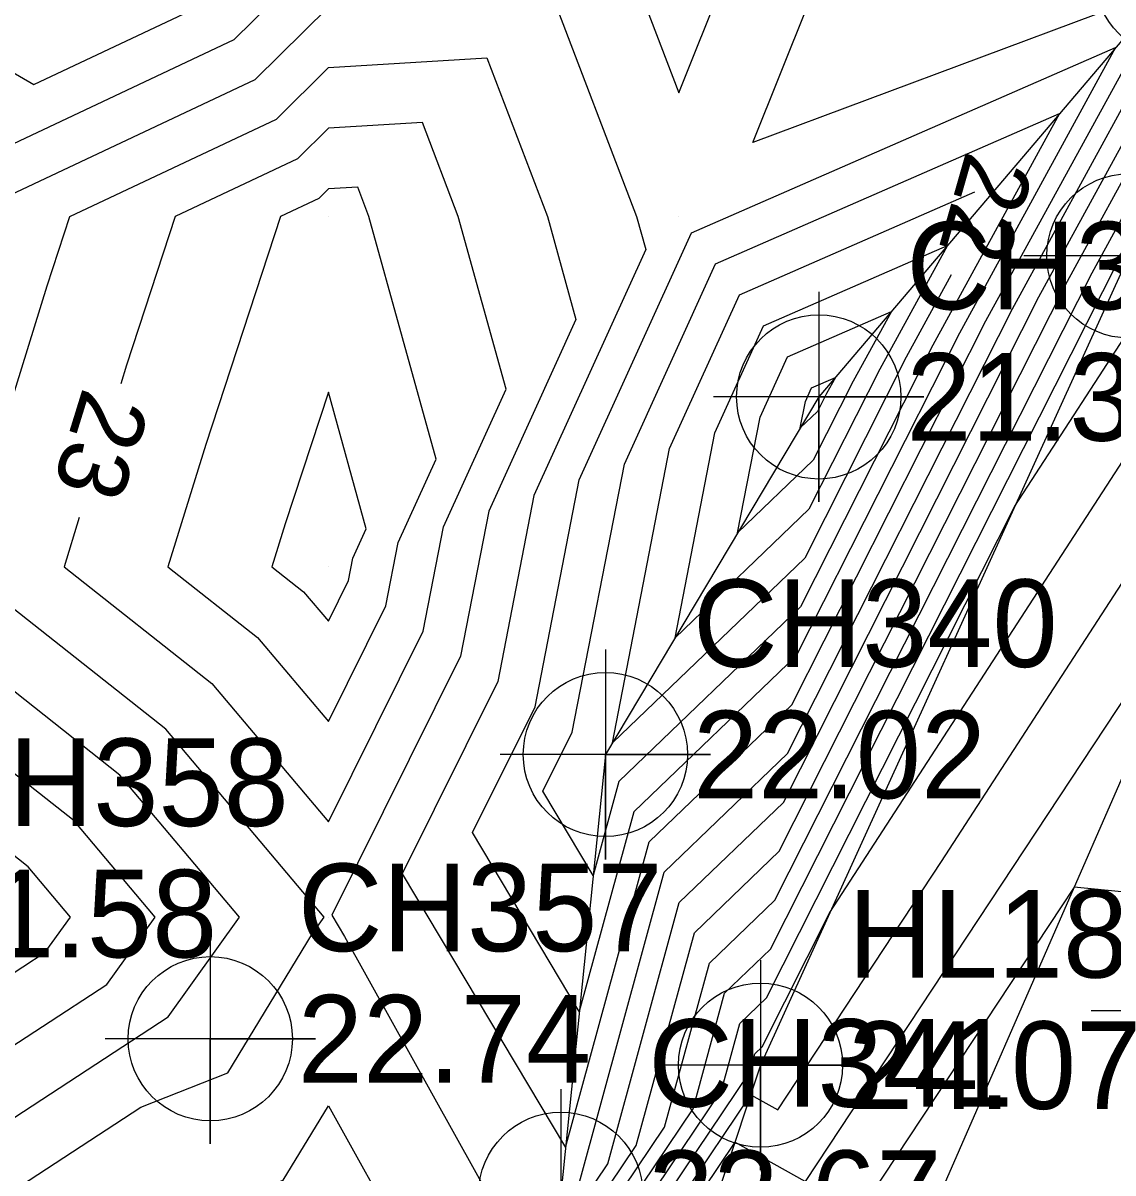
# Model space of a CAD drawing. Extents: x 2531902 to 2533249, y 715219 to 716099.
# Drawn here: x 2532801.29 to 2532832.39, y 715572.69 to 715605.53 of the extents above; entities that cross this region are included whole.
import ezdxf

# ---------------------------------------------------------------- set-up
doc = ezdxf.new("R2010")
doc.units = 0
for name, color, linetype in [('DTM Contours Major', 7, 'Continuous'), ('DTM Contours Major Text', 7, 'Continuous'), ('DTM Contours Minor', 7, 'Continuous'), ('Exist DTM Breakline', 7, 'Continuous'), ('Exist DTM Breakline Cogo Elevation', 7, 'Continuous'), ('Exist DTM Breakline Cogo Number', 7, 'Continuous'), ('Exist DTM Breakline Cogo Point CELL', 7, 'Continuous'), ('Exist DTM Drainline', 7, 'Continuous'), ('Exist DTM QL2 LIDAR Elevation Point', 7, 'Continuous'), ('Exist DTM Regular Point CELL', 7, 'Continuous'), ('Exist DTM Regular Point Cogo Elevation', 7, 'Continuous'), ('Exist DTM Regular Point Cogo Number', 7, 'Continuous'), ('Exist Roads Soil Cogo Point CELL', 7, 'Continuous')]:
    doc.layers.add(name, color=color, linetype=linetype)

msp = doc.modelspace()

# ---------------------------------------------------------------- linework, layer by layer
at = {"layer": 'DTM Contours Major'}
for points in [[(2532791.4, 715554.435), (2532792.067, 715557.933), (2532792.869, 715560), (2532794.025, 715565.975), (2532800, 715568.961), (2532800.889, 715569.111), (2532802.4, 715570), (2532808.714, 715572.49), (2532810, 715574.608), (2532812.181, 715570.686), (2532814.067, 715567.411), (2532813.398, 715561.929), (2532816.552, 715570.834), (2532817.976, 715572.954), (2532820.015, 715580.415), (2532822.987, 715583.272), (2532830.281, 715597.708), (2532833.72, 715603.995), (2532839.452, 715610.247), (2532839.495, 715610.298)], [(2532813.283, 715591.138), (2532815.07, 715595.07), (2532813.705, 715600), (2532812.683, 715602.683), (2532810, 715602.519), (2532809.121, 715601.649), (2532805.628, 715600), (2532804.242, 715595.758), (2532804.076, 715595.225)], [(2532818.106, 715584.973), (2532819.74, 715593.375), (2532821.734, 715597.765), (2532828.453, 715600.702)], [(2532827.776, 715598.331), (2532826.493, 715595.986), (2532823.595, 715590.25), (2532818.106, 715584.973)], [(2532816.309, 715567.061), (2532822.029, 715575.574), (2532822.171, 715576.095), (2532822.379, 715576.294), (2532824.314, 715580.125), (2532834.07, 715595.172)], [(2532802.892, 715591.404), (2532802.457, 715590), (2532806.67, 715586.67), (2532810, 715582.721), (2532812.706, 715588.166), (2532813.283, 715591.138)]]:
    msp.add_lwpolyline(points, dxfattribs=at)
at = {"layer": 'DTM Contours Minor'}
for points in [[(2532800, 715604.694), (2532801.593, 715603.77), (2532806.704, 715606.184), (2532810, 715609.445), (2532819.083, 715610), (2532820.17, 715610.294), (2532824.846, 715615.648), (2532828.788, 715619.347), (2532829.955, 715620.078), (2532830.004, 715620.089), (2532836.592, 715620.993)], [(2532816.26, 715566.306), (2532822.053, 715574.927), (2532822.823, 715574.495), (2532827.503, 715581.581), (2532834.828, 715592.88), (2532842.241, 715605.151), (2532843.096, 715603.185), (2532845.749, 715611.189), (2532851.137, 715619.865), (2532853.378, 715619.981), (2532856.522, 715615.626), (2532856.577, 715608.1), (2532858.751, 715598.418), (2532859.746, 715597.674), (2532860.482, 715597.724), (2532858.698, 715593.363), (2532858.5, 715592.772), (2532854.09, 715579.617), (2532854.851, 715576.054), (2532852.242, 715565.505)], [(2532800.095, 715600.225), (2532807.913, 715603.916), (2532810, 715605.982), (2532816.371, 715606.371), (2532818.797, 715600), (2532819.058, 715599.058), (2532815.866, 715592.033), (2532814.834, 715586.723), (2532812.107, 715581.236), (2532816.768, 715573.416), (2532819.153, 715582.143), (2532823.23, 715586.063), (2532828.765, 715597.019), (2532834.068, 715606.71), (2532831.907, 715605.766), (2532822.113, 715602.113), (2532825.275, 715610), (2532827.585, 715612.646), (2532830, 715614.912), (2532835.701, 715619.851)], [(2532800.844, 715601.998), (2532807.309, 715605.05), (2532810, 715607.714), (2532818.215, 715608.215), (2532820, 715603.529), (2532822.594, 715610), (2532826.216, 715614.147), (2532830, 715617.698), (2532832.579, 715619.933)], [(2532847.705, 715569.849), (2532849.505, 715575.216), (2532853.41, 715594.081), (2532853.465, 715594.349), (2532852.389, 715599.142), (2532852.28, 715613.906), (2532851.071, 715615.58), (2532850.209, 715615.536), (2532848.137, 715612.199), (2532843.88, 715599.358), (2532844.511, 715592.438), (2532839.033, 715587.843), (2532835.553, 715590.397), (2532835.464, 715590.406), (2532823.606, 715572.454), (2532821.604, 715573.577), (2532816.212, 715565.552)], [(2532817.165, 715572.43), (2532819.584, 715581.279), (2532823.108, 715584.668), (2532829.523, 715597.363), (2532833.979, 715605.508)], [(2532820.362, 715599.533), (2532832.468, 715604.827), (2532828.008, 715596.674), (2532823.352, 715587.459), (2532818.721, 715583.008), (2532817.162, 715577.302), (2532814.115, 715582.414), (2532815.898, 715586.002), (2532817.157, 715592.48), (2532820.362, 715599.533)], [(2532800, 715591.644), (2532801.977, 715598.023), (2532802.623, 715600), (2532808.517, 715602.783), (2532810, 715604.251), (2532814.527, 715604.527), (2532816.251, 715600), (2532817.064, 715597.064), (2532814.575, 715591.585), (2532813.77, 715587.444), (2532810.099, 715580.058), (2532810.463, 715579.447), (2532814.867, 715571.53)], [(2532821.048, 715598.649), (2532830.868, 715602.943), (2532827.25, 715596.33), (2532823.473, 715588.855), (2532818.29, 715583.872), (2532817.557, 715581.187), (2532816.123, 715583.593), (2532816.962, 715585.28), (2532818.448, 715592.928), (2532821.048, 715598.649)], [(2532816.503, 715570.08), (2532818.787, 715573.478), (2532820.446, 715579.551), (2532822.865, 715581.877), (2532831.038, 715598.052), (2532833.462, 715602.482)], [(2532816.455, 715569.325), (2532819.597, 715574.002), (2532820.878, 715578.687), (2532822.743, 715580.481), (2532831.796, 715598.397), (2532833.203, 715600.969)], [(2532811.992, 715590.69), (2532813.076, 715593.076), (2532811.158, 715600), (2532810.839, 715600.839), (2532810, 715600.787), (2532809.725, 715600.516), (2532808.633, 715600), (2532806.506, 715593.494), (2532805.423, 715590), (2532807.98, 715587.98), (2532810, 715585.584), (2532811.642, 715588.887), (2532811.992, 715590.69)], [(2532819.893, 715587.97), (2532821.031, 715593.823), (2532822.42, 715596.88), (2532827.669, 715599.175), (2532825.735, 715595.641), (2532823.716, 715591.646), (2532819.893, 715587.97)], [(2532816.406, 715568.57), (2532820.408, 715574.526), (2532821.309, 715577.823), (2532822.622, 715579.086), (2532832.553, 715598.741)], [(2532816.358, 715567.816), (2532821.218, 715575.05), (2532821.74, 715576.959), (2532822.5, 715577.69), (2532829.596, 715591.734), (2532833.311, 715597.464)], [(2532821.68, 715590.967), (2532822.322, 715594.27), (2532823.107, 715595.996), (2532826.069, 715597.291), (2532824.978, 715595.297), (2532823.838, 715593.041), (2532821.68, 715590.967)], [(2532823.467, 715593.963), (2532823.613, 715594.718), (2532823.793, 715595.112), (2532824.469, 715595.408), (2532824.22, 715594.952), (2532823.96, 715594.437), (2532823.467, 715593.963)], [(2532810.701, 715590.243), (2532811.082, 715591.082), (2532810, 715594.989), (2532808.771, 715591.229), (2532808.39, 715590), (2532809.289, 715589.289), (2532810, 715588.446), (2532810.578, 715589.608), (2532810.701, 715590.243)], [(2532800, 715571.537), (2532804.65, 715574.576), (2532807.131, 715575.555), (2532809.545, 715579.531), (2532809.881, 715580), (2532805.361, 715585.361), (2532800, 715589.597)], [(2532800, 715573.604), (2532805.43, 715577.154), (2532807.467, 715580), (2532804.051, 715584.051), (2532800, 715587.253)], [(2532829.193, 715527.168), (2532831.066, 715530.483), (2532832.888, 715534.551), (2532840.608, 715556.07), (2532841.778, 715561.209), (2532842.211, 715563.408), (2532842.911, 715566.611), (2532846.93, 715587.374), (2532840.977, 715584.212), (2532835.804, 715579.873), (2532834.96, 715580.492), (2532831.285, 715580.854), (2532824.389, 715570.413), (2532821.155, 715572.227), (2532816.163, 715564.797), (2532811.044, 715550.341), (2532806.188, 715529.933), (2532808.716, 715532.979), (2532806.85, 715527.886)], [(2532800, 715575.672), (2532803.675, 715578.074), (2532805.053, 715580), (2532802.742, 715582.742), (2532800, 715584.908)], [(2532800, 715577.739), (2532801.919, 715578.994), (2532802.64, 715580), (2532801.432, 715581.432), (2532800, 715582.564)]]:
    msp.add_lwpolyline(points, dxfattribs=at)
at = {"layer": 'Exist DTM Breakline'}
for points in [[(2532850.523, 715624.043), (2532846.504, 715620.874), (2532841.706, 715614.127), (2532832.845, 715598.874), (2532822.333, 715575.771), (2532815.557, 715555.383), (2532805.828, 715528.954), (2532795.014, 715502.43), (2532778.718, 715468.977), (2532762.354, 715433.263), (2532743.219, 715394.959), (2532734.198, 715371.89), (2532718.026, 715339.994), (2532703.206, 715306.913)], [(2532851.508, 715621.597), (2532844.842, 715610.805), (2532835.568, 715590.645), (2532825.478, 715567.576), (2532808.054, 715526.629), (2532792.366, 715492.682), (2532777.25, 715459.478), (2532760.672, 715423.843), (2532743.255, 715387.785), (2532725.494, 715349.638), (2532709.856, 715316.842), (2532704.172, 715304.494)]]:
    msp.add_lwpolyline(points, dxfattribs=at)
at = {"layer": 'Exist DTM Breakline Cogo Point CELL'}
for points in [[(2532832.845, 715601.874), (2532832.845, 715595.874), (2532832.845, 715598.874), (2532835.845, 715598.874), (2532829.845, 715598.874)], [(2532823.996, 715597.85), (2532823.996, 715591.85), (2532823.996, 715594.85), (2532826.996, 715594.85), (2532820.996, 715594.85)], [(2532817.907, 715587.639), (2532817.907, 715581.639), (2532817.907, 715584.639), (2532820.907, 715584.639), (2532814.907, 715584.639)], [(2532822.333, 715578.771), (2532822.333, 715572.771), (2532822.333, 715575.771), (2532825.333, 715575.771), (2532819.333, 715575.771)], [(2532816.632, 715575.085), (2532816.632, 715569.085), (2532816.632, 715572.085), (2532819.632, 715572.085), (2532813.632, 715572.085)]]:
    msp.add_lwpolyline(points, dxfattribs=at)
for centre in [(2532834.214, 715606.883), (2532832.845, 715598.874), (2532823.996, 715594.85), (2532817.907, 715584.639), (2532822.333, 715575.771), (2532816.632, 715572.085)]:
    msp.add_circle(centre, 2.344, dxfattribs=at)
at = {"layer": 'Exist DTM Drainline'}
msp.add_lwpolyline([(2532840.626, 715622.249), (2532834.214, 715606.883), (2532823.996, 715594.85), (2532817.907, 715584.639), (2532816.632, 715572.085), (2532808.971, 715548.025), (2532795.108, 715512.754), (2532774.804, 715467.828), (2532771.712, 715461.016)], dxfattribs=at)
at = {"layer": 'Exist DTM QL2 LIDAR Elevation Point'}
for p, q in [((2532810, 715600), (2532810, 715600)), ((2532820, 715600), (2532820, 715600)), ((2532810, 715590), (2532810, 715590)), ((2532810, 715580), (2532810, 715580))]:
    msp.add_line(p, q, dxfattribs=at)
at = {"layer": 'Exist DTM Regular Point CELL'}
msp.add_lwpolyline([(2532806.63, 715579.525), (2532806.63, 715573.525), (2532806.63, 715576.525), (2532809.63, 715576.525), (2532803.63, 715576.525)], dxfattribs=at)
msp.add_circle((2532806.63, 715576.525), 2.344, dxfattribs=at)
at = {"layer": 'Exist Roads Soil Cogo Point CELL'}
msp.add_lwpolyline([(2532834.77, 715574.322), (2532834.77, 715580.322), (2532834.77, 715577.322), (2532837.77, 715577.322), (2532831.77, 715577.322)], dxfattribs=at)

# ---------------------------------------------------------------- texts
at = {"layer": 'DTM Contours Major Text'}
for s, rotation, p in [('22', 254.072, (2532828.222, 715601.927)), ('23', 252.78, (2532803.012, 715595.168))]:
    msp.add_text(s, height=2, rotation=rotation, dxfattribs=at).set_placement(p)
at = {"layer": 'Exist DTM Breakline Cogo Elevation'}
for s, p in [('21.34', (2532826.496, 715593.6)), ('22.02', (2532820.407, 715583.389)), ('24.07', (2532824.833, 715574.521)), ('22.67', (2532819.132, 715570.835))]:
    msp.add_text(s, height=2.5, dxfattribs=at).set_placement(p)
at = {"layer": 'Exist DTM Breakline Cogo Number'}
for s, p in [('CH339', (2532826.496, 715597.35)), ('CH340', (2532820.407, 715587.139)), ('HL182', (2532824.833, 715578.271)), ('CH341', (2532819.132, 715574.585))]:
    msp.add_text(s, height=2.5, dxfattribs=at).set_placement(p)
at = {"layer": 'Exist DTM Regular Point Cogo Elevation'}
for s, p in [('21.58', (2532798.462, 715578.849)), ('22.74', (2532809.13, 715575.275))]:
    msp.add_text(s, height=2.5, dxfattribs=at).set_placement(p)
at = {"layer": 'Exist DTM Regular Point Cogo Number'}
for s, p in [('CH358', (2532798.462, 715582.599)), ('CH357', (2532809.13, 715579.025))]:
    msp.add_text(s, height=2.5, dxfattribs=at).set_placement(p)

doc.saveas('drawing.dxf')
